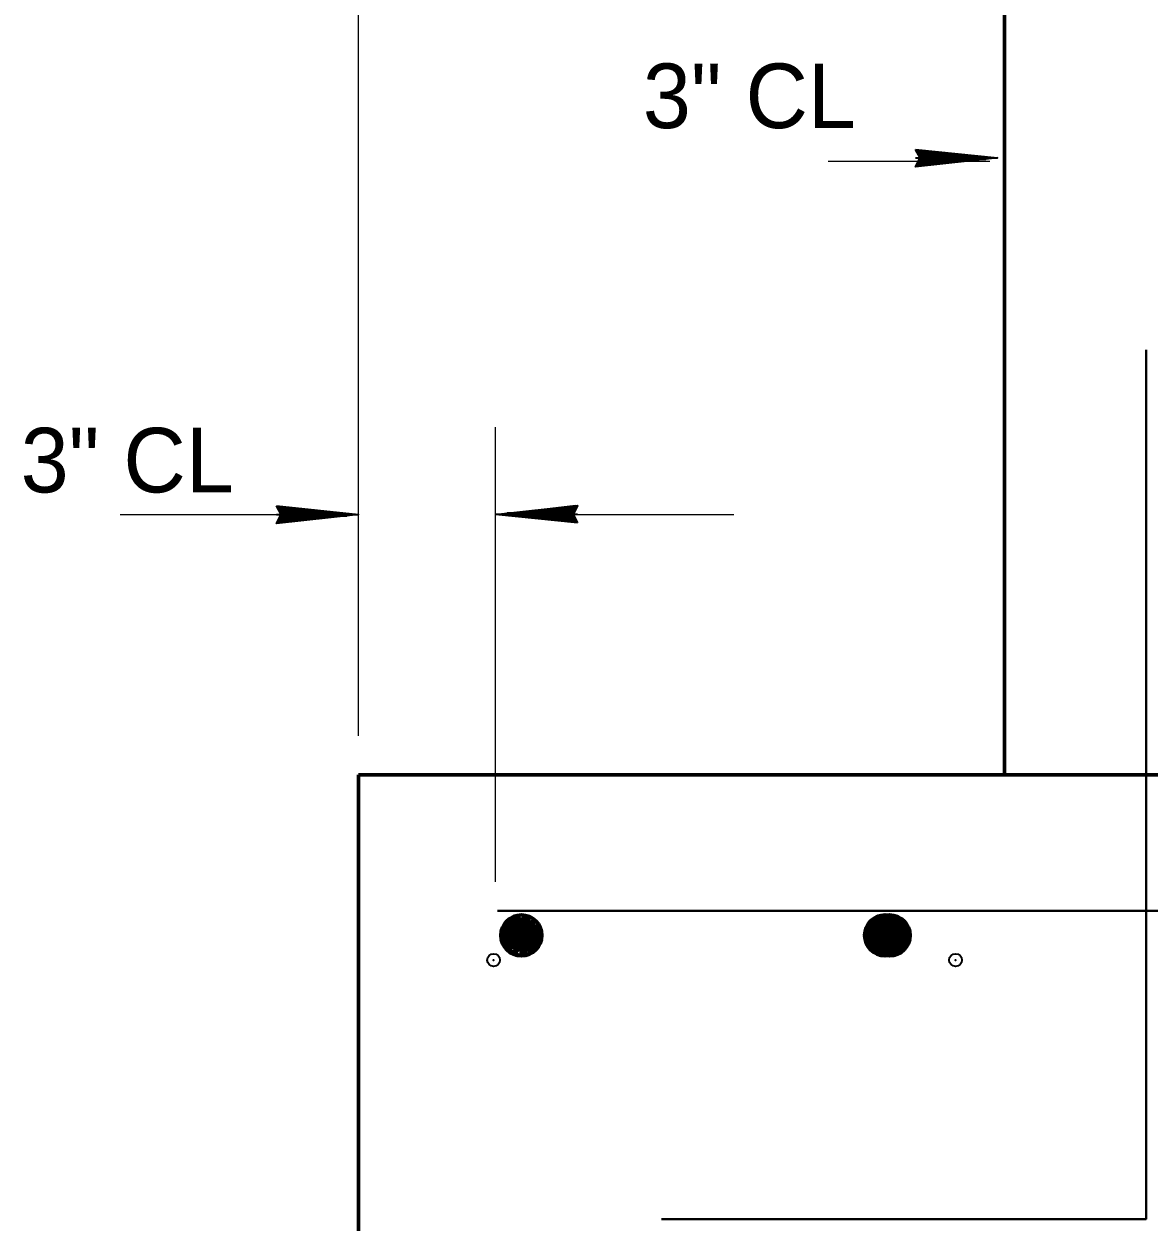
# Model space of a CAD drawing. Extents: x 4.49 to 7.69, y 0.28 to 2.27.
# Drawn here: x 5.8132 to 5.9583, y 1.898 to 2.0525 of the extents above; entities that cross this region are included whole.
import ezdxf

# ---------------------------------------------------------------- set-up
doc = ezdxf.new("R2010")
doc.units = 0
doc.header["$LTSCALE"] = 0.0033
doc.header["$PDMODE"] = 32
doc.header["$PDSIZE"] = 0.00165
doc.layers.add('1', color=7, linetype='Continuous', lineweight=35)

msp = doc.modelspace()

# ---------------------------------------------------------------- linework, layer by layer
at = {"layer": '1', "lineweight": 13}
for p, q in [((5.856333, 1.960667), (5.856333, 2.10925)), ((5.916917, 2.034833), (5.93775, 2.034833)), ((5.874, 1.941833), (5.874, 2.0005)), ((5.825583, 1.98925), (5.846417, 1.98925)), ((5.883917, 1.98925), (5.90475, 1.98925))]:
    msp.add_line(p, q, dxfattribs=at)
at = {"layer": '1'}
for p, q in [((5.928417, 2.03625), (5.93625, 2.035333)), ((5.928417, 2.03625), (5.93625, 2.035333)), ((5.928417, 2.036167), (5.93625, 2.035333)), ((5.928417, 2.036083), (5.93625, 2.03525)), ((5.928417, 2.036083), (5.93625, 2.035083)), ((5.928167, 2.03525), (5.93875, 2.03525)), ((5.928333, 2.034583), (5.935667, 2.035333)), ((5.928417, 2.034417), (5.93575, 2.03525)), ((5.928417, 2.034333), (5.93575, 2.035083)), ((5.928417, 2.034167), (5.93575, 2.035)), ((5.845917, 1.988583), (5.85325, 1.989333)), ((5.846, 1.99025), (5.853833, 1.989333)), ((5.846, 1.99025), (5.853833, 1.989333)), ((5.846, 1.990167), (5.853833, 1.989333)), ((5.846, 1.990083), (5.853833, 1.98925)), ((5.846, 1.990083), (5.853833, 1.989083)), ((5.884333, 1.988417), (5.8765, 1.989417)), ((5.884333, 1.990333), (5.877, 1.9895)), ((5.884333, 1.990167), (5.877, 1.989417)), ((5.884333, 1.990083), (5.877, 1.98925)), ((5.884417, 1.989917), (5.877083, 1.989167)), ((5.84575, 1.98925), (5.856333, 1.98925)), ((5.846, 1.988417), (5.853333, 1.98925)), ((5.846, 1.988333), (5.853333, 1.989083)), ((5.846, 1.988167), (5.853333, 1.989)), ((5.884583, 1.98925), (5.874, 1.98925)), ((5.884333, 1.988417), (5.8765, 1.98925)), ((5.884333, 1.98825), (5.8765, 1.989167)), ((5.884333, 1.98825), (5.8765, 1.989167)), ((5.884333, 1.988333), (5.8765, 1.989167))]:
    msp.add_line(p, q, dxfattribs=at)
at = {"layer": '1', "lineweight": 60}
for p, q in [((5.856333, 1.872333), (5.856333, 1.955667)), ((5.939667, 1.955667), (6.002167, 1.955667)), ((5.8755, 1.9365), (5.875333, 1.933583)), ((5.87575, 1.9365), (5.8755, 1.933583)), ((5.875917, 1.9365), (5.87575, 1.9335)), ((5.876083, 1.9365), (5.875833, 1.9335)), ((5.87625, 1.9365), (5.876083, 1.9335)), ((5.8765, 1.9365), (5.876333, 1.9335)), ((5.87675, 1.9365), (5.8765, 1.9335)), ((5.876833, 1.936417), (5.876667, 1.9335)), ((5.877, 1.936417), (5.876833, 1.9335)), ((5.877167, 1.936417), (5.877, 1.9335)), ((5.877417, 1.936417), (5.877167, 1.9335)), ((5.877583, 1.936417), (5.877417, 1.9335)), ((5.877833, 1.936333), (5.877583, 1.933417)), ((5.878083, 1.936333), (5.877833, 1.933417)), ((5.87825, 1.936333), (5.878083, 1.933417)), ((5.878333, 1.936333), (5.878167, 1.933417)), ((5.8785, 1.936333), (5.878333, 1.933417)), ((5.878583, 1.936333), (5.878417, 1.933417)), ((5.878833, 1.93625), (5.878583, 1.933333)), ((5.879, 1.93625), (5.878833, 1.933333)), ((5.879167, 1.93625), (5.878917, 1.933333)), ((5.879333, 1.93625), (5.879167, 1.933333)), ((5.879583, 1.93625), (5.879417, 1.933333)), ((5.879833, 1.934333), (5.879667, 1.936167)), ((5.922417, 1.9365), (5.92225, 1.933583)), ((5.922667, 1.9365), (5.922417, 1.933583)), ((5.922833, 1.9365), (5.922667, 1.9335)), ((5.923, 1.9365), (5.92275, 1.9335)), ((5.923, 1.9365), (5.922833, 1.933583)), ((5.92325, 1.9365), (5.923, 1.933583)), ((5.923167, 1.9365), (5.923, 1.9335)), ((5.923417, 1.9365), (5.92325, 1.9335)), ((5.923417, 1.9365), (5.92325, 1.9335)), ((5.923583, 1.9365), (5.923333, 1.9335)), ((5.923667, 1.9365), (5.923417, 1.9335)), ((5.92375, 1.9365), (5.923583, 1.9335)), ((5.92375, 1.936417), (5.923583, 1.9335)), ((5.923917, 1.936417), (5.92375, 1.9335)), ((5.924, 1.9365), (5.923833, 1.9335)), ((5.924083, 1.936417), (5.923917, 1.9335)), ((5.92425, 1.9365), (5.924, 1.9335)), ((5.924333, 1.936417), (5.924083, 1.9335)), ((5.924333, 1.936417), (5.924167, 1.9335)), ((5.9245, 1.936417), (5.924333, 1.9335)), ((5.9245, 1.936417), (5.924333, 1.9335)), ((5.924667, 1.936417), (5.9245, 1.9335)), ((5.92475, 1.936333), (5.9245, 1.933417)), ((5.924917, 1.936417), (5.924667, 1.9335)), ((5.925, 1.936333), (5.92475, 1.933417)), ((5.925083, 1.936417), (5.924917, 1.9335)), ((5.925167, 1.936333), (5.925, 1.933417)), ((5.925333, 1.936333), (5.925083, 1.933417)), ((5.92525, 1.936333), (5.925083, 1.933417)), ((5.925417, 1.936333), (5.92525, 1.933417)), ((5.925583, 1.936333), (5.925333, 1.933417)), ((5.9255, 1.936333), (5.925333, 1.933417)), ((5.92575, 1.93625), (5.9255, 1.933333)), ((5.92575, 1.936333), (5.925583, 1.933417)), ((5.925833, 1.936333), (5.925667, 1.933417)), ((5.925917, 1.93625), (5.92575, 1.933333)), ((5.926, 1.936333), (5.925833, 1.933417)), ((5.926083, 1.93625), (5.925833, 1.933333)), ((5.926083, 1.936333), (5.925917, 1.933417)), ((5.926333, 1.93625), (5.926083, 1.933333)), ((5.92625, 1.93625), (5.926083, 1.933333)), ((5.9265, 1.93625), (5.926333, 1.933333)), ((5.9265, 1.93625), (5.926333, 1.933333)), ((5.926667, 1.93625), (5.926417, 1.933333)), ((5.92675, 1.934333), (5.926583, 1.936167)), ((5.926833, 1.93625), (5.926667, 1.933333)), ((5.927083, 1.93625), (5.926917, 1.933333)), ((5.927333, 1.934333), (5.927167, 1.936167)), ((5.879833, 1.934333), (5.875083, 1.933583)), ((5.92675, 1.934333), (5.922, 1.933583)), ((5.927333, 1.934333), (5.922583, 1.933583))]:
    msp.add_line(p, q, dxfattribs=at)
at = {"layer": '1', "lineweight": 40}
for p, q in [((5.87425, 1.938083), (6.172, 1.938083)), ((5.875667, 1.936833), (5.8795, 1.936167)), ((5.877583, 1.936), (5.878917, 1.937)), ((5.879667, 1.936167), (5.878417, 1.937333)), ((5.922583, 1.936833), (5.926417, 1.936167)), ((5.923167, 1.936833), (5.927, 1.936167)), ((5.9245, 1.936), (5.925833, 1.937)), ((5.925083, 1.936), (5.926417, 1.937)), ((5.926583, 1.936167), (5.925333, 1.937333)), ((5.927167, 1.936167), (5.925917, 1.937333)), ((5.87525, 1.9365), (5.879833, 1.934333)), ((5.875417, 1.9355), (5.87925, 1.934833)), ((5.875417, 1.935333), (5.87925, 1.934583)), ((5.8755, 1.936083), (5.879417, 1.935333)), ((5.8755, 1.935917), (5.879417, 1.935167)), ((5.8755, 1.935667), (5.879333, 1.934917)), ((5.875583, 1.9365), (5.8795, 1.935833)), ((5.875583, 1.936333), (5.8795, 1.935583)), ((5.922167, 1.9365), (5.92675, 1.934333)), ((5.922333, 1.9355), (5.926167, 1.934833)), ((5.922333, 1.935333), (5.926167, 1.934583)), ((5.922417, 1.936083), (5.926333, 1.935333)), ((5.922417, 1.935917), (5.926333, 1.935167)), ((5.922417, 1.935667), (5.92625, 1.934917)), ((5.9225, 1.9365), (5.926417, 1.935833)), ((5.9225, 1.936333), (5.926417, 1.935583)), ((5.92275, 1.9365), (5.927333, 1.934333)), ((5.922917, 1.9355), (5.92675, 1.934833)), ((5.922917, 1.935333), (5.92675, 1.934583)), ((5.923, 1.936083), (5.926917, 1.935333)), ((5.923, 1.935917), (5.926917, 1.935167)), ((5.923, 1.935667), (5.926833, 1.934917)), ((5.923083, 1.9365), (5.927, 1.935833)), ((5.923083, 1.936333), (5.927, 1.935583)), ((5.875083, 1.93375), (5.878917, 1.933)), ((5.875167, 1.93425), (5.879083, 1.9335)), ((5.875167, 1.934083), (5.879, 1.933333)), ((5.875167, 1.933833), (5.879, 1.933167)), ((5.87525, 1.934667), (5.879167, 1.933917)), ((5.875333, 1.935083), (5.879167, 1.934333)), ((5.875333, 1.934917), (5.879167, 1.934167)), ((5.922, 1.93375), (5.925833, 1.933)), ((5.922083, 1.93425), (5.926, 1.9335)), ((5.922083, 1.934083), (5.925917, 1.933333)), ((5.922083, 1.933833), (5.925917, 1.933167)), ((5.922167, 1.934667), (5.926083, 1.933917)), ((5.92225, 1.935083), (5.926083, 1.934333)), ((5.92225, 1.934917), (5.926083, 1.934167)), ((5.922583, 1.93375), (5.926417, 1.933)), ((5.922667, 1.93425), (5.926583, 1.9335)), ((5.922667, 1.934083), (5.9265, 1.933333)), ((5.922667, 1.933833), (5.9265, 1.933167)), ((5.92275, 1.934667), (5.926667, 1.933917)), ((5.922833, 1.935083), (5.926667, 1.934333)), ((5.922833, 1.934917), (5.926667, 1.934167)), ((5.875083, 1.933583), (5.878917, 1.932833)), ((5.879417, 1.933333), (5.875667, 1.932917)), ((5.922, 1.933583), (5.925833, 1.932833)), ((5.922583, 1.933583), (5.926417, 1.932833)), ((5.926333, 1.933333), (5.922583, 1.932917)), ((5.926917, 1.933333), (5.923167, 1.932917))]:
    msp.add_line(p, q, dxfattribs=at)
at = {"layer": '1', "lineweight": 60}
for points in [[(5.856333, 1.955667), (5.939667, 1.955667), (5.939667, 2.059833)], [(5.878917, 1.932833), (5.878917, 1.937), (5.87725, 1.932333), (5.87775, 1.9375), (5.875667, 1.932917), (5.876417, 1.937417), (5.878, 1.932417), (5.874833, 1.93575), (5.879667, 1.936167), (5.876417, 1.9325), (5.878417, 1.937333), (5.87525, 1.9365), (5.875083, 1.933583)], [(5.875667, 1.932917), (5.877167, 1.935167), (5.875, 1.936083), (5.877, 1.9375), (5.877167, 1.93525), (5.878833, 1.932917), (5.874833, 1.93525), (5.877583, 1.936)], [(5.878417, 1.937333), (5.877167, 1.935167), (5.879417, 1.933333)], [(5.925833, 1.932833), (5.925833, 1.937), (5.924167, 1.932333), (5.924667, 1.9375), (5.922583, 1.932917), (5.923333, 1.937417), (5.924917, 1.932417), (5.92175, 1.93575), (5.926583, 1.936167), (5.923333, 1.9325), (5.925333, 1.937333), (5.922167, 1.9365), (5.922, 1.933583)], [(5.922583, 1.932917), (5.924083, 1.935167), (5.921917, 1.936083), (5.923917, 1.9375), (5.924083, 1.93525), (5.92575, 1.932917), (5.92175, 1.93525), (5.9245, 1.936)], [(5.926417, 1.932833), (5.926417, 1.937), (5.92475, 1.932333), (5.92525, 1.9375), (5.923167, 1.932917), (5.923917, 1.937417), (5.9255, 1.932417), (5.922333, 1.93575), (5.927167, 1.936167), (5.923917, 1.9325), (5.925917, 1.937333), (5.92275, 1.9365), (5.922583, 1.933583)], [(5.923167, 1.932917), (5.924667, 1.935167), (5.9225, 1.936083), (5.9245, 1.9375), (5.924667, 1.93525), (5.926333, 1.932917), (5.922333, 1.93525), (5.925083, 1.936)], [(5.925333, 1.937333), (5.924083, 1.935167), (5.926333, 1.933333)], [(5.925917, 1.937333), (5.924667, 1.935167), (5.926917, 1.933333)], [(5.874667, 1.934833), (5.879833, 1.9355), (5.87525, 1.9365)], [(5.921583, 1.934833), (5.92675, 1.9355), (5.922167, 1.9365)], [(5.922167, 1.934833), (5.927333, 1.9355), (5.92275, 1.9365)]]:
    msp.add_lwpolyline(points, dxfattribs=at)
at = {"layer": '1'}
for points in [[(5.928167, 2.036333), (5.93875, 2.03525), (5.928167, 2.034083), (5.92875, 2.03525)], [(5.928917, 2.035333), (5.933583, 2.035417), (5.933583, 2.035333), (5.932667, 2.035333), (5.928917, 2.035417), (5.931917, 2.0355), (5.92875, 2.035583), (5.931, 2.035667), (5.92875, 2.03575), (5.93225, 2.0355), (5.936917, 2.035333), (5.936, 2.035083), (5.93725, 2.035083), (5.928917, 2.035083), (5.931333, 2.034917), (5.92875, 2.034917), (5.934083, 2.035333), (5.92875, 2.034667)], [(5.84575, 1.990333), (5.856333, 1.98925), (5.84575, 1.988083), (5.846333, 1.98925)], [(5.8465, 1.989333), (5.851167, 1.989417), (5.851167, 1.989333), (5.85025, 1.989333), (5.8465, 1.989417), (5.8495, 1.9895), (5.846333, 1.989583), (5.848583, 1.989667), (5.846333, 1.98975), (5.849833, 1.9895), (5.8545, 1.989333), (5.853583, 1.989083), (5.854833, 1.989083), (5.8465, 1.989083), (5.848917, 1.988917), (5.846333, 1.988917), (5.851667, 1.989333), (5.846333, 1.988667)], [(5.884583, 1.988167), (5.874, 1.98925), (5.884583, 1.990417), (5.884, 1.98925)], [(5.883833, 1.989167), (5.879167, 1.989083), (5.879167, 1.989167), (5.880083, 1.989167), (5.883833, 1.989083), (5.880833, 1.989), (5.884, 1.988917), (5.88175, 1.988833), (5.884, 1.98875), (5.8805, 1.989), (5.875833, 1.989167), (5.87675, 1.989417), (5.8755, 1.989417), (5.883833, 1.989417), (5.881417, 1.989583), (5.884, 1.989583), (5.878667, 1.989167), (5.884, 1.989833)]]:
    msp.add_lwpolyline(points, close=True, dxfattribs=at)
for points in [[(5.928917, 2.035333), (5.9285, 2.036083), (5.92875, 2.035833), (5.928917, 2.0355), (5.929167, 2.035583), (5.929, 2.035917), (5.928833, 2.035167), (5.928667, 2.034667), (5.928417, 2.03425)], [(5.8465, 1.989333), (5.846083, 1.990083), (5.846333, 1.989833), (5.8465, 1.9895), (5.84675, 1.989583), (5.846583, 1.989917), (5.846417, 1.989167), (5.84625, 1.988667), (5.846, 1.98825)], [(5.883833, 1.989167), (5.88425, 1.988417), (5.884, 1.988667), (5.883833, 1.989), (5.883583, 1.988917), (5.88375, 1.988583), (5.883917, 1.989333), (5.884083, 1.989833), (5.884333, 1.99025)]]:
    msp.add_lwpolyline(points, dxfattribs=at)
at = {"layer": '1', "lineweight": 40}
for points in [[(5.895417, 1.898333), (5.957917, 1.898333), (5.957917, 2.0105)], [(5.875083, 1.933583), (5.877167, 1.932333), (5.878917, 1.932833), (5.879833, 1.934333)], [(5.922, 1.933583), (5.924083, 1.932333), (5.925833, 1.932833), (5.92675, 1.934333)], [(5.922583, 1.933583), (5.924667, 1.932333), (5.926417, 1.932833), (5.927333, 1.934333)]]:
    msp.add_lwpolyline(points, dxfattribs=at)
at = {"layer": '1', "lineweight": 60}
for centre in [(5.877333, 1.934933), (5.92425, 1.934933), (5.924833, 1.934933)]:
    msp.add_circle(centre, 0.00264, dxfattribs=at)
at = {"layer": '1'}
for p in [(5.87675, 1.933917), (5.87375, 1.93175), (5.933333, 1.93175)]:
    msp.add_point(p, dxfattribs=at)

# ---------------------------------------------------------------- texts
for p in [(5.893, 2.039083), (5.81275, 1.992083)]:
    msp.add_text('3" CL', height=0.008334, dxfattribs=at).set_placement(p)

doc.saveas('drawing.dxf')
